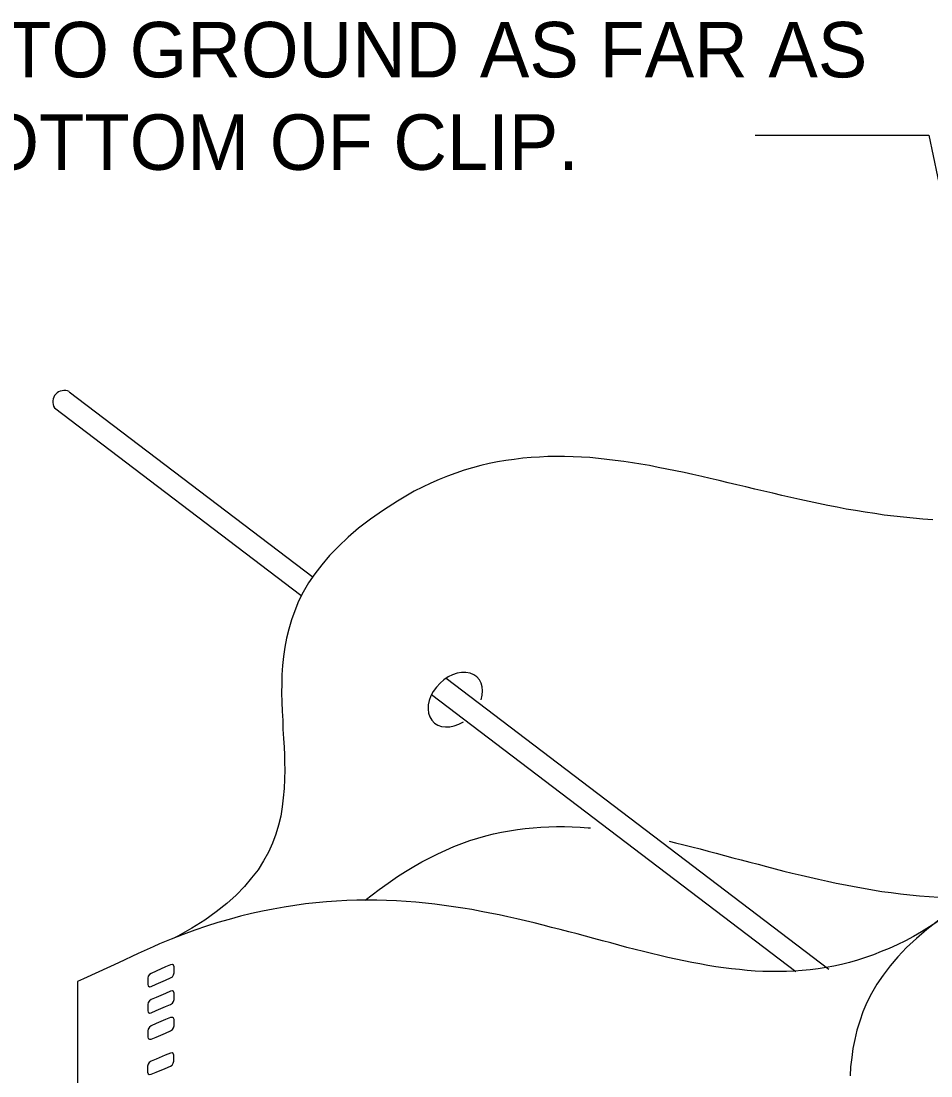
# Model space of a CAD drawing. Extents: x 638850 to 644908, y 297188 to 298900.
# Drawn here: x 638911.2 to 638960.4, y 297748.7 to 297805.7 of the extents above; entities that cross this region are included whole.
import ezdxf

# ---------------------------------------------------------------- set-up
doc = ezdxf.new("R2010")
doc.units = 0
for name, color, linetype in [('1', 7, 'Continuous'), ('16', 7, 'Continuous'), ('2', 7, 'Continuous'), ('7', 7, 'Continuous')]:
    doc.layers.add(name, color=color, linetype=linetype)

msp = doc.modelspace()

# ---------------------------------------------------------------- linework, layer by layer
at = {"layer": '1'}
for p, q in [((638960.314, 297799.559), (638973.153, 297738.184)), ((638913.819, 297785.694), (638927.015, 297775.662)), ((638913.019, 297784.821), (638926.345, 297774.689)), ((638934.209, 297770.193), (638954.908, 297754.456)), ((638933.419, 297769.311), (638953.129, 297754.326))]:
    msp.add_line(p, q, dxfattribs=at)
msp.add_arc((638913.546, 297785.141), 0.617, 63.7169, 211.2583, dxfattribs=at)
msp.add_ellipse((638934.705, 297769.036), major_axis=(-1.203, -1.196), ratio=0.717222, start_param=2.18443, end_param=7.533439, dxfattribs=at)
at = {"layer": '16'}
for points in [[(638919.296, 297753.987), (638919.404, 297754.049), (638919.466, 297754.157), (638919.496, 297754.265), (638919.496, 297754.265), (638919.496, 297754.34), (638919.496, 297754.51), (638919.496, 297754.589), (638919.496, 297754.589), (638919.466, 297754.681), (638919.404, 297754.713), (638919.296, 297754.697), (638919.296, 297754.697), (638919.031, 297754.589), (638918.524, 297754.357), (638918.259, 297754.232), (638918.259, 297754.232), (638918.167, 297754.17), (638918.092, 297754.078), (638918.076, 297753.97), (638918.076, 297753.97), (638918.076, 297753.879), (638918.076, 297753.725), (638918.076, 297753.63), (638918.076, 297753.63), (638918.092, 297753.555), (638918.167, 297753.506), (638918.259, 297753.522), (638918.259, 297753.522), (638918.524, 297753.646), (638919.031, 297753.862), (638919.296, 297753.987), (638919.296, 297753.987), (638919.296, 297753.987)], [(638919.296, 297752.55), (638919.404, 297752.626), (638919.466, 297752.72), (638919.496, 297752.828), (638919.496, 297752.828), (638919.496, 297752.92), (638919.496, 297753.074), (638919.496, 297753.169), (638919.496, 297753.169), (638919.466, 297753.244), (638919.404, 297753.29), (638919.296, 297753.277), (638919.296, 297753.277), (638919.031, 297753.152), (638918.524, 297752.936), (638918.259, 297752.812), (638918.259, 297752.812), (638918.167, 297752.75), (638918.092, 297752.658), (638918.076, 297752.55), (638918.076, 297752.55), (638918.076, 297752.456), (638918.076, 297752.302), (638918.076, 297752.21), (638918.076, 297752.21), (638918.092, 297752.132), (638918.167, 297752.086), (638918.259, 297752.102), (638918.259, 297752.102), (638918.524, 297752.226), (638919.031, 297752.442), (638919.296, 297752.55), (638919.296, 297752.55), (638919.296, 297752.55)], [(638919.296, 297751.13), (638919.404, 297751.189), (638919.466, 297751.284), (638919.496, 297751.392), (638919.496, 297751.392), (638919.496, 297751.484), (638919.496, 297751.638), (638919.496, 297751.732), (638919.496, 297751.732), (638919.466, 297751.808), (638919.404, 297751.854), (638919.296, 297751.84), (638919.296, 297751.84), (638919.031, 297751.732), (638918.524, 297751.516), (638918.259, 297751.392), (638918.259, 297751.392), (638918.167, 297751.33), (638918.092, 297751.222), (638918.076, 297751.13), (638918.076, 297751.13), (638918.076, 297751.036), (638918.076, 297750.882), (638918.076, 297750.79), (638918.076, 297750.79), (638918.092, 297750.712), (638918.167, 297750.666), (638918.259, 297750.682), (638918.259, 297750.682), (638918.524, 297750.79), (638919.031, 297751.006), (638919.296, 297751.13), (638919.296, 297751.13), (638919.296, 297751.13)], [(638919.296, 297749.213), (638919.388, 297749.275), (638919.45, 297749.367), (638919.48, 297749.478), (638919.48, 297749.478), (638919.48, 297749.569), (638919.48, 297749.723), (638919.48, 297749.815), (638919.48, 297749.815), (638919.45, 297749.893), (638919.388, 297749.939), (638919.296, 297749.923), (638919.296, 297749.923), (638919.018, 297749.815), (638918.524, 297749.599), (638918.246, 297749.491), (638918.246, 297749.491), (638918.151, 297749.416), (638918.092, 297749.321), (638918.059, 297749.213), (638918.059, 297749.213), (638918.059, 297749.137), (638918.059, 297748.967), (638918.059, 297748.889), (638918.059, 297748.889), (638918.092, 297748.797), (638918.151, 297748.765), (638918.246, 297748.781), (638918.246, 297748.781), (638918.524, 297748.889), (638919.018, 297749.092), (638919.296, 297749.213), (638919.296, 297749.213), (638919.296, 297749.213)]]:
    msp.add_lwpolyline(points, dxfattribs=at)
at = {"layer": '2'}
for points in [[(638956.359, 297779.267), (638955.852, 297779.346), (638955.357, 297779.454), (638954.847, 297779.546), (638954.354, 297779.654), (638953.843, 297779.749), (638953.348, 297779.857), (638952.855, 297779.978), (638952.36, 297780.086), (638951.883, 297780.196), (638951.388, 297780.318), (638950.909, 297780.426), (638950.414, 297780.55), (638949.937, 297780.658), (638949.458, 297780.766), (638948.981, 297780.889), (638948.499, 297780.997), (638948.038, 297781.105), (638947.557, 297781.213), (638947.08, 297781.321), (638946.616, 297781.414), (638946.153, 297781.508), (638945.673, 297781.6), (638945.212, 297781.693), (638944.746, 297781.771), (638944.283, 297781.846), (638943.822, 297781.909), (638943.356, 297781.969), (638942.908, 297782.032), (638942.447, 297782.082), (638941.981, 297782.127), (638941.533, 297782.156), (638941.072, 297782.172), (638940.609, 297782.185), (638940.159, 297782.185), (638939.711, 297782.185), (638939.25, 297782.156), (638938.802, 297782.14), (638938.354, 297782.095), (638937.888, 297782.032), (638937.441, 297781.969), (638936.995, 297781.895), (638936.532, 297781.801), (638936.082, 297781.693), (638935.634, 297781.571), (638935.186, 297781.447), (638934.738, 297781.292), (638934.277, 297781.123), (638933.827, 297780.937), (638933.379, 297780.752), (638932.932, 297780.534), (638932.47, 297780.304), (638932.023, 297780.039), (638931.573, 297779.778), (638931.573, 297779.778), (638930.817, 297779.283), (638930.121, 297778.806), (638929.473, 297778.311), (638928.9, 297777.818), (638928.378, 297777.321), (638927.896, 297776.826), (638927.48, 297776.333), (638927.111, 297775.838), (638926.771, 297775.348), (638926.476, 297774.853), (638926.231, 297774.36), (638926.015, 297773.849), (638925.844, 297773.354), (638925.691, 297772.857), (638925.565, 297772.364), (638925.475, 297771.869), (638925.412, 297771.376), (638925.349, 297770.881), (638925.318, 297770.386), (638925.318, 297769.896), (638925.304, 297769.401), (638925.318, 297768.906), (638925.333, 297768.411), (638925.367, 297767.916), (638925.381, 297767.439), (638925.412, 297766.944), (638925.441, 297766.465), (638925.441, 297766.465), (638925.457, 297766.048), (638925.457, 297765.646), (638925.475, 297765.247), (638925.475, 297765.247), (638925.457, 297764.737), (638925.441, 297764.226)], [(638960.53, 297778.761), (638959.988, 297778.806), (638959.464, 297778.851), (638958.942, 297778.898), (638958.431, 297778.959), (638957.907, 297779.022), (638957.396, 297779.098), (638956.869, 297779.175), (638956.359, 297779.267)], [(638925.441, 297764.226), (638925.395, 297763.731), (638925.333, 297763.237), (638925.258, 297762.743), (638925.133, 297762.249), (638924.993, 297761.755), (638924.809, 297761.277), (638924.593, 297760.796), (638924.329, 297760.318), (638924.037, 297759.84), (638923.681, 297759.392), (638923.295, 297758.928), (638922.846, 297758.466), (638922.339, 297758.018), (638921.766, 297757.553), (638921.148, 297757.105), (638920.454, 297756.673), (638919.696, 297756.241), (638919.558, 297756.168)], [(638929.822, 297758.189), (638930.585, 297758.774), (638931.064, 297759.114), (638931.573, 297759.472), (638931.573, 297759.472), (638932.005, 297759.746), (638932.455, 297760.012), (638932.887, 297760.257), (638933.334, 297760.489), (638933.766, 297760.705), (638934.198, 297760.905), (638934.633, 297761.092), (638935.065, 297761.26), (638935.497, 297761.416), (638935.915, 297761.539), (638936.347, 297761.663), (638936.779, 297761.771), (638937.211, 297761.863), (638937.627, 297761.94), (638938.062, 297762.016), (638938.478, 297762.064), (638938.91, 297762.111), (638939.326, 297762.142), (638939.76, 297762.158), (638940.177, 297762.174), (638940.609, 297762.174), (638941.023, 297762.158), (638941.459, 297762.142), (638941.891, 297762.111), (638942.014, 297762.097)], [(638946.27, 297761.379), (638946.616, 297761.294), (638947.064, 297761.184), (638947.496, 297761.076), (638947.944, 297760.968), (638948.376, 297760.846), (638948.823, 297760.734), (638949.271, 297760.61), (638949.721, 297760.489), (638950.169, 297760.365), (638950.63, 297760.241), (638951.078, 297760.133), (638951.544, 297760.012), (638952.007, 297759.888), (638952.468, 297759.762), (638952.934, 297759.654), (638953.411, 297759.546), (638953.875, 297759.438), (638954.354, 297759.33), (638954.833, 297759.222), (638955.312, 297759.114), (638955.805, 297759.024), (638956.284, 297758.929), (638956.777, 297758.837), (638957.272, 297758.743), (638957.783, 297758.666), (638958.276, 297758.605), (638958.786, 297758.542), (638959.297, 297758.479), (638959.821, 297758.434), (638960.332, 297758.389), (638960.854, 297758.356)], [(638947.064, 297754.913), (638946.632, 297755.005), (638946.2, 297755.098), (638945.768, 297755.206), (638945.32, 297755.316), (638944.888, 297755.424), (638944.438, 297755.532), (638943.99, 297755.64), (638943.558, 297755.764), (638943.111, 297755.887), (638942.663, 297755.993), (638942.202, 297756.117), (638941.752, 297756.243), (638941.288, 297756.367), (638940.84, 297756.488), (638940.379, 297756.612), (638939.913, 297756.72), (638939.45, 297756.844), (638938.971, 297756.965), (638938.507, 297757.075), (638938.03, 297757.183), (638937.551, 297757.291), (638937.072, 297757.399), (638936.577, 297757.492), (638936.1, 297757.586), (638935.605, 297757.678), (638935.11, 297757.755), (638934.601, 297757.831), (638934.106, 297757.908), (638933.598, 297757.971), (638933.089, 297758.032), (638932.563, 297758.081), (638932.052, 297758.126), (638931.528, 297758.155), (638930.988, 297758.173), (638930.463, 297758.189), (638929.921, 297758.189), (638929.381, 297758.189), (638928.839, 297758.173), (638928.285, 297758.142), (638927.73, 297758.095), (638927.156, 297758.047), (638926.6, 297757.987), (638926.031, 297757.908), (638925.441, 297757.816), (638924.856, 297757.71), (638924.267, 297757.6), (638923.682, 297757.462), (638923.079, 297757.323), (638922.478, 297757.152), (638921.859, 297756.981), (638921.241, 297756.783), (638920.608, 297756.567), (638919.99, 297756.337), (638919.342, 297756.085), (638918.712, 297755.827), (638918.712, 297755.827), (638918.367, 297755.669), (638917.551, 297755.3), (638916.486, 297754.805), (638915.42, 297754.312), (638914.585, 297753.941), (638914.261, 297753.786), (638914.261, 297753.786), (638914.261, 297733.324)], [(638960.809, 297757.044), (638960.361, 297756.751), (638959.929, 297756.488), (638959.497, 297756.225), (638959.05, 297755.993), (638958.613, 297755.777), (638958.181, 297755.577), (638957.749, 297755.408), (638957.317, 297755.237), (638956.885, 297755.084), (638956.453, 297754.947), (638956.035, 297754.821), (638955.603, 297754.711), (638955.171, 297754.618), (638954.757, 297754.544), (638954.325, 297754.481), (638953.906, 297754.42), (638953.474, 297754.387), (638953.058, 297754.357), (638952.626, 297754.326), (638952.207, 297754.326), (638951.775, 297754.326), (638951.343, 297754.342), (638950.925, 297754.357), (638950.493, 297754.387), (638950.074, 297754.436), (638949.642, 297754.481), (638949.21, 297754.528), (638948.794, 297754.589), (638948.362, 297754.666), (638947.928, 297754.744), (638947.496, 297754.821), (638947.064, 297754.913)], [(638960.863, 297757.102), (638960.213, 297756.61), (638959.644, 297756.115), (638959.119, 297755.624), (638958.638, 297755.129), (638958.222, 297754.636), (638957.853, 297754.141), (638957.511, 297753.644), (638957.218, 297753.151), (638956.973, 297752.656), (638956.755, 297752.146), (638956.584, 297751.653), (638956.433, 297751.158), (638956.309, 297750.663), (638956.215, 297750.172), (638956.152, 297749.677), (638956.089, 297749.182), (638956.059, 297748.687)]]:
    msp.add_lwpolyline(points, dxfattribs=at)
at = {"layer": '7'}
msp.add_line((638950.922, 297799.559), (638960.314, 297799.559), dxfattribs=at)

# ---------------------------------------------------------------- texts
at = {"layer": '1'}
for s, p in [('INTO GROUND AS FAR AS', (638906.393, 297802.692)), ('BOTTOM OF CLIP.', (638906.393, 297797.692))]:
    msp.add_text(s, height=3, dxfattribs=at).set_placement(p)

doc.saveas('drawing.dxf')
